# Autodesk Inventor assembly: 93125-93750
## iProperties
Author: Administrator
Shininess: 64.0
Angle Display Precision: 2
Document Length Units: 11272
Document Angle Units: 11286
Document Time Units: 11279
Document Mass Units: 11290
Document Length Units Precision: 3
Document Angle Units Precision: 2
Compacted: True
PropertySet Name: _Private Model Information
Created: 2002-03
Part Number: 93125-93750
Document SubType Name: Assembly
Designer: Administrator
Control State: 0
Master: False
Checked Out: False
PropertySet Name: Design Tracking Control
Density: 0.0
Volumn: 0.0
Area: 0.0
PropertySet Name: Model Information
